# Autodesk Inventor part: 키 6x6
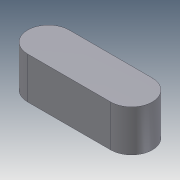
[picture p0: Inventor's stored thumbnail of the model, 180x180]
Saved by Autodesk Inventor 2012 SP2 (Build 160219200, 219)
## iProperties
Company: 한국ATC센터
Created: 2013-01
Part Number: 키 6x6
Document SubType Name: Modeling
Designer: KYOUNG IL JANG
Density: 7.25 g/cm^3
Material: 주철
Mass: 4.36193 g
Surface Area: 4.57646 cm^2
Volume: 0.601646 cm^3
Author: KYOUNG IL JANG
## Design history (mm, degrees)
sketch "스케치1"
  geometry: L1 (-6, -3)-(6, -3); L2 (6, 3)-(-6, 3); A1 r 3 centre (6, 0) between (6, -3) and (6, 3); A2 r 3 centre (-6, 0) between (-6, 3) and (-6, -3); 2 further points
  constraints: 4 end point, 4 point on circle, 4 tangent, 2 centre point, 1 horizontal, 1 horizontal alignment, 1 midpoint, 1 parallel, 1 vertical alignment
  dimensions: "d0" = 18 dimension on A1 A2; "d1" = 6 distance between parallel lines of L1 L2
extrude "돌출1" new body sketch "스케치1" stored distance "d2" = 6; taper "d3" = 0 deg
node "솔리드1"
